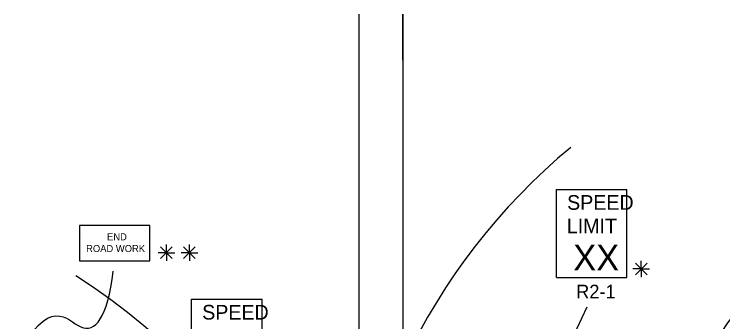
# Model space of a CAD drawing. Extents: x 16554 to 19508, y 5694 to 7079.
# Drawn here: x 16792.7 to 17179.3, y 6806.3 to 6974.1 of the extents above; entities that cross this region are included whole.
import ezdxf

# ---------------------------------------------------------------- set-up
doc = ezdxf.new("R2010")
doc.units = 0
for name, color, linetype in [('ALI_LEGAL_EX', 7, 'Continuous'), ('TRAFFIC_SIGNS_PR', 7, 'Continuous'), ('TYPICAL_TEXT_DIMEN_PR', 7, 'Continuous')]:
    doc.layers.add(name, color=color, linetype=linetype)

msp = doc.modelspace()

# ---------------------------------------------------------------- linework, layer by layer
at = {"layer": 'ALI_LEGAL_EX'}
for p, q in [((16980.68, 6974.12), (16980.68, 6155.98)), ((17004.68, 6974.12), (17004.68, 6155.98)), ((16980.68, 6877.04), (16980.68, 6013.12)), ((17004.68, 6877.04), (17004.68, 6013.12))]:
    msp.add_line(p, q, dxfattribs=at)
msp.add_lwpolyline([(17004.68, 6949.12), (17004.68, 6974.12)], dxfattribs=at)
for centre, radius, start, end in [((17313.01, 6639.38), 340, 129.5666, 180), ((16629.65, 6525.15), 364, 0, 57.2958)]:
    msp.add_arc(centre, radius, start, end, dxfattribs=at)
at = {"layer": 'TRAFFIC_SIGNS_PR'}
for p, q in [((17088.62, 6878.56), (17127.01, 6878.56)), ((17088.62, 6830.56), (17088.62, 6878.56)), ((17127.01, 6830.56), (17127.01, 6878.56)), ((17088.62, 6830.56), (17127.01, 6830.56)), ((16889.53, 6818.69), (16927.92, 6818.69)), ((16889.53, 6770.69), (16889.53, 6818.69)), ((16927.92, 6770.69), (16927.92, 6818.69))]:
    msp.add_line(p, q, dxfattribs=at)
msp.add_lwpolyline([(16828.37, 6839.64), (16866.77, 6839.64), (16866.77, 6858.84), (16828.37, 6858.84)], close=True, dxfattribs=at)
at = {"layer": 'TYPICAL_TEXT_DIMEN_PR'}
for p, q in [((16872.61, 6847.2), (16878.98, 6840.83)), ((16878.98, 6847.2), (16872.61, 6840.83)), ((16875.79, 6844.02), (16875.79, 6848.47)), ((16891.54, 6847.2), (16885.16, 6840.83)), ((16885.17, 6847.2), (16891.54, 6840.83)), ((16888.35, 6844.02), (16888.35, 6848.47)), ((16875.79, 6844.02), (16871.26, 6844.02)), ((16875.79, 6844.02), (16878.98, 6844.02)), ((16875.79, 6844.02), (16880.27, 6844.02)), ((16875.79, 6844.02), (16875.79, 6839.52)), ((16888.35, 6844.02), (16883.82, 6844.02)), ((16888.35, 6844.02), (16891.54, 6844.02)), ((16888.35, 6844.02), (16892.83, 6844.02)), ((16888.35, 6844.02), (16888.35, 6839.52)), ((17134.82, 6835.17), (17134.82, 6839.63)), ((17131.64, 6838.36), (17138.01, 6831.99)), ((17138.01, 6838.36), (17131.64, 6831.99)), ((17134.82, 6835.17), (17130.29, 6835.17)), ((17134.82, 6835.17), (17138.01, 6835.17)), ((17134.82, 6835.17), (17139.3, 6835.17)), ((17134.82, 6835.17), (17134.82, 6830.67)), ((17077.28, 6754.99), (17105.34, 6814.46))]:
    msp.add_line(p, q, dxfattribs=at)
for points in [[(17174.97, 6794.28), (17195.01, 6830.85), (17212.06, 6800.75), (17226.02, 6817.04), (17229.02, 6842.74)], [(16792.71, 6785.53), (16812.75, 6822.09), (16829.8, 6792), (16843.76, 6808.28), (16846.76, 6833.99)]]:
    msp.add_open_spline(points, degree=3, dxfattribs=at)

# ---------------------------------------------------------------- texts
at = {"layer": 'TRAFFIC_SIGNS_PR'}
for s, height, p in [('SPEED', 8, (17094.38, 6867.42)), ('LIMIT', 8, (17094.22, 6854.62)), ('END', 3.831, (16843.37, 6850.77)), ('ROAD WORK', 3.831, (16831.97, 6844.38)), ('XX', 14.031, (17097.73, 6834.32)), ('R2-1', 7.44, (17099.29, 6819.12)), ('SPEED', 8, (16895.29, 6807.55))]:
    msp.add_text(s, height=height, dxfattribs=at).set_placement(p)

doc.saveas('drawing.dxf')
